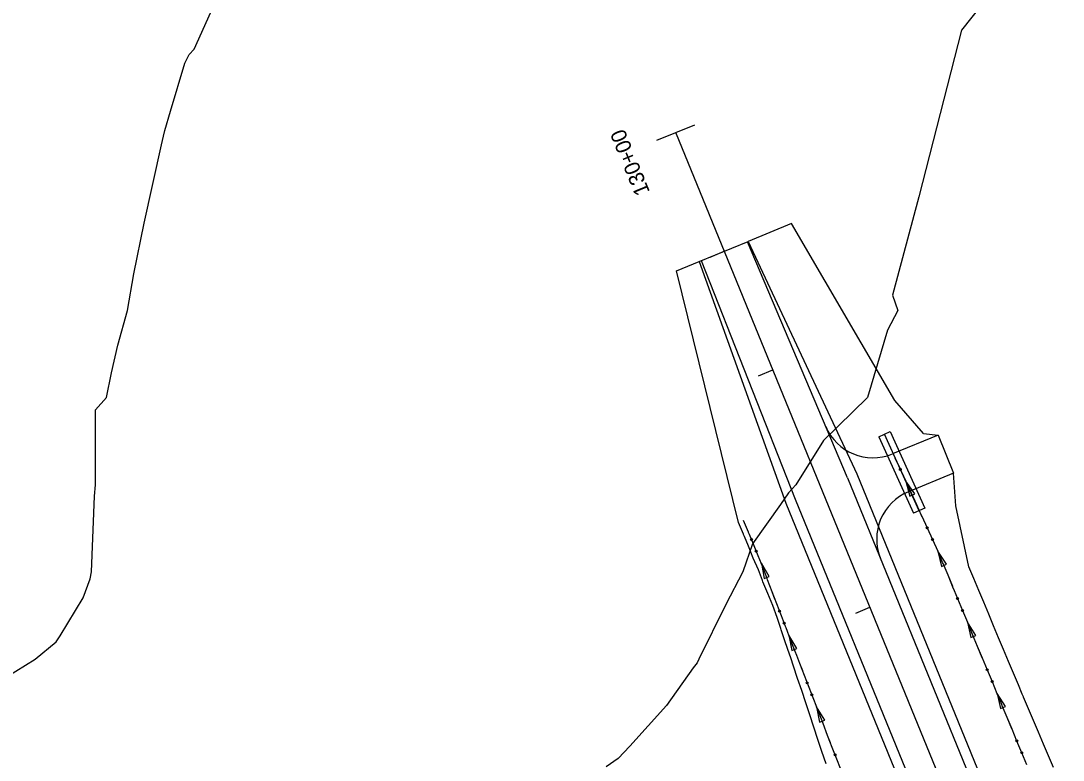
# Model space of a CAD drawing. Extents: x 916431 to 921570, y 1763982 to 1768032.
# Drawn here: x 918187 to 918593.5, y 1765886.5 to 1766174.8 of the extents above; entities that cross this region are included whole.
import ezdxf

# ---------------------------------------------------------------- set-up
doc = ezdxf.new("R2010")
doc.units = 0
for name, color, linetype in [('R_Drainage', 7, 'Continuous'), ('R_Horz Alg', 7, 'Continuous'), ('R_Horz Alg Stationing', 7, 'Continuous'), ('R_Proposed Const Limits', 7, 'Continuous'), ('R_Proposed Road', 7, 'Continuous'), ('R_SFHA', 7, 'Continuous'), ('R_Shld', 7, 'Continuous'), ('R_Special Ditch', 7, 'Continuous')]:
    doc.layers.add(name, color=color, linetype=linetype)

msp = doc.modelspace()

# ---------------------------------------------------------------- linework, layer by layer
at = {"layer": 'R_Drainage'}
for p, q in [((918523.8, 1766013.64), (918526, 1766014.64)), ((918526, 1766014.64), (918539.56, 1765984.79)), ((918521.6, 1766012.64), (918523.8, 1766013.64)), ((918521.6, 1766012.64), (918535.16, 1765982.79)), ((918537.36, 1765983.79), (918523.8, 1766013.64)), ((918539.56, 1765984.79), (918535.16, 1765982.79))]:
    msp.add_line(p, q, dxfattribs=at)
at = {"layer": 'R_Horz Alg'}
msp.add_line((918565.23, 1765830.96), (918442.38, 1766131.25), dxfattribs=at)
at = {"layer": 'R_Horz Alg Stationing'}
for points in [[(918434.97, 1766128.22), (918449.78, 1766134.28)], [(918474.69, 1766036.42), (918480.24, 1766038.7)], [(918512.55, 1765943.87), (918518.11, 1765946.14)]]:
    msp.add_lwpolyline(points, dxfattribs=at)
at = {"layer": 'R_Proposed Const Limits'}
for p, q in [((918539.04, 1766013.83), (918544.69, 1766013.2)), ((918551.55, 1765985.72), (918550.75, 1765998.39)), ((918556.72, 1765961.94), (918551.55, 1765985.72))]:
    msp.add_line(p, q, dxfattribs=at)
for points in [[(918539.04, 1766013.83), (918527.87, 1766026.76), (918487.58, 1766095.72), (918470.65, 1766088.8)], [(918466.82, 1765979.18), (918442.63, 1766077.33), (918451.49, 1766080.96)], [(918500.99, 1765885.12), (918499.38, 1765889.86), (918497.81, 1765894.62), (918496.27, 1765899.4), (918494.66, 1765904.14), (918493.13, 1765908.91), (918491.51, 1765913.65), (918489.9, 1765918.4), (918488.34, 1765923.16), (918487.24, 1765926.36), (918486.71, 1765927.9), (918485.09, 1765932.64), (918483.5, 1765937.39), (918483.35, 1765937.82), (918481.87, 1765942.12), (918480.22, 1765946.85), (918478.32, 1765951.47), (918476.4, 1765956.09), (918476.19, 1765956.6), (918474.59, 1765960.75), (918472.59, 1765965.34), (918470.69, 1765969.96), (918469.19, 1765973.67), (918468.83, 1765974.52), (918468.8, 1765974.59), (918466.82, 1765979.18)], [(918589.75, 1765883.61), (918587.74, 1765888.2), (918585.75, 1765892.78), (918583.82, 1765897.4), (918581.89, 1765902.01), (918579.91, 1765906.6), (918578.02, 1765911.12), (918577.98, 1765911.21), (918577.54, 1765912.28), (918576.06, 1765915.83), (918574.08, 1765920.42), (918572.16, 1765925.04), (918570.24, 1765929.66), (918568.28, 1765934.26), (918566.36, 1765938.87), (918564.44, 1765943.49), (918562.49, 1765948.09), (918560.57, 1765952.71), (918559.28, 1765955.83), (918558.66, 1765957.33), (918556.72, 1765961.94)]]:
    msp.add_lwpolyline(points, dxfattribs=at)
at = {"layer": 'R_Proposed Road'}
for p, q in [((918451.49, 1766080.96), (918470.65, 1766088.8)), ((918509.35, 1765996.59), (918470.32, 1766088.66)), ((918452.29, 1766081.28), (918488.99, 1765988.25)), ((918544.69, 1766013.2), (918526.85, 1766005.9)), ((918544.69, 1766013.2), (918550.75, 1765998.39)), ((918550.75, 1765998.39), (918533.17, 1765991.2)), ((918509.35, 1765996.59), (918575.41, 1765835.12)), ((918488.99, 1765988.25), (918555.05, 1765826.79))]:
    msp.add_line(p, q, dxfattribs=at)
for centre, start, end in [((918519.28, 1766024.42), 202.9725, 292.2503), ((918540.74, 1765972.69), 112.2503, 202.2503)]:
    msp.add_arc(centre, 20, start, end, dxfattribs=at)
at = {"layer": 'R_SFHA'}
for points in [[(918593.47, 1766221.24), (918553.81, 1766171.17), (918537.22, 1766106.16), (918526.91, 1766067.79), (918529.03, 1766061.85), (918524.91, 1766054.15), (918517.2, 1766027.89), (918499.95, 1766011.15), (918489.2, 1765993.9), (918486.31, 1765990.76), (918483.2, 1765986.16), (918472.27, 1765970.87), (918468.52, 1765959.93), (918461.9, 1765947.2), (918451.4, 1765925.92), (918450.72, 1765924.41), (918449.22, 1765922.53), (918438.71, 1765907.78), (918424.42, 1765891.92), (918419.93, 1765887.21), (918415.21, 1765883.98)], [(918177.34, 1765916.53), (918192.52, 1765925.91), (918200.74, 1765932.64), (918202.25, 1765935), (918211.29, 1765949.77), (918213.98, 1765957.24), (918214.52, 1765959.92), (918215.71, 1765989.5), (918216.12, 1765993.88), (918216.08, 1766023.11), (918220.32, 1766027.88), (918222.27, 1766037.55), (918224.8, 1766048.38), (918228.58, 1766061.88), (918231.05, 1766076.12), (918235.12, 1766095.84), (918241.87, 1766126.44), (918242.57, 1766129.85), (918243.16, 1766131.98), (918245.29, 1766139.51), (918250.87, 1766158.23), (918252.59, 1766161.63), (918254.6, 1766163.8), (918262.29, 1766180.79)]]:
    msp.add_lwpolyline(points, dxfattribs=at)
at = {"layer": 'R_Shld'}
for p, q in [((918470.65, 1766088.8), (918513.06, 1765998.1)), ((918455.75, 1766082.7), (918461.31, 1766084.97)), ((918451.49, 1766080.96), (918485.29, 1765986.74)), ((918513.06, 1765998.1), (918579.11, 1765836.64)), ((918485.29, 1765986.74), (918551.35, 1765825.28))]:
    msp.add_line(p, q, dxfattribs=at)
at = {"layer": 'R_Special Ditch'}
for p, q in [((918532.09, 1765995.33), (918533.64, 1765989.43)), ((918535.56, 1765990.31), (918532.09, 1765995.33)), ((918533.64, 1765989.43), (918535.56, 1765990.31)), ((918544.63, 1765968.03), (918545.96, 1765962.08)), ((918547.91, 1765962.9), (918544.63, 1765968.03)), ((918475.84, 1765963.39), (918476.83, 1765957.38)), ((918478.82, 1765958.08), (918475.84, 1765963.39)), ((918545.96, 1765962.08), (918547.91, 1765962.9)), ((918476.83, 1765957.38), (918478.82, 1765958.08)), ((918556.17, 1765940.3), (918557.5, 1765934.35)), ((918559.46, 1765935.16), (918556.17, 1765940.3)), ((918486.48, 1765935.31), (918487.66, 1765929.33)), ((918489.63, 1765930.09), (918486.48, 1765935.31)), ((918557.5, 1765934.35), (918559.46, 1765935.16)), ((918487.66, 1765929.33), (918489.63, 1765930.09)), ((918567.71, 1765912.56), (918569.04, 1765906.62)), ((918571, 1765907.43), (918567.71, 1765912.56)), ((918497.32, 1765907.29), (918498.49, 1765901.31)), ((918500.47, 1765902.08), (918497.32, 1765907.29)), ((918569.04, 1765906.62), (918571, 1765907.43)), ((918498.49, 1765901.31), (918500.47, 1765902.08))]:
    msp.add_line(p, q, dxfattribs=at)
for points in [[(918579.29, 1765884.74), (918577.37, 1765889.36), (918575.45, 1765893.97), (918573.53, 1765898.59), (918571.61, 1765903.2), (918569.73, 1765907.73), (918569.69, 1765907.82), (918569.24, 1765908.89), (918567.77, 1765912.44), (918565.85, 1765917.05), (918563.92, 1765921.67), (918562, 1765926.29), (918560.08, 1765930.9), (918558.16, 1765935.52), (918556.24, 1765940.14), (918554.32, 1765944.75), (918552.4, 1765949.37), (918551.1, 1765952.49), (918550.48, 1765953.98), (918548.56, 1765958.6), (918546.63, 1765963.22), (918546.46, 1765963.63), (918544.71, 1765967.83), (918542.63, 1765972.38), (918540.54, 1765976.93), (918538.45, 1765981.48), (918538.22, 1765981.98), (918536.36, 1765986.03), (918534.28, 1765990.57), (918532.19, 1765995.12), (918530.52, 1765998.76), (918530.13, 1765999.6), (918530.1, 1765999.67), (918528.01, 1766004.22)], [(918538.35, 1765981.69), (918538.22, 1765981.98), (918536.36, 1765986.03), (918534.28, 1765990.57), (918532.19, 1765995.12), (918532.09, 1765995.33)], [(918506.61, 1765883.26), (918505.22, 1765886.85), (918503.42, 1765891.51), (918501.61, 1765896.18), (918499.81, 1765900.84), (918498.01, 1765905.51), (918496.2, 1765910.17), (918494.4, 1765914.83), (918492.59, 1765919.5), (918490.79, 1765924.16), (918489.57, 1765927.31), (918488.99, 1765928.83), (918487.18, 1765933.49), (918485.38, 1765938.16), (918485.22, 1765938.58), (918483.58, 1765942.82), (918481.77, 1765947.48), (918479.97, 1765952.15), (918478.16, 1765956.81), (918477.97, 1765957.33), (918476.49, 1765961.53), (918474.58, 1765966.15), (918472.68, 1765970.77), (918471.15, 1765974.47), (918470.8, 1765975.32), (918470.77, 1765975.4), (918468.86, 1765980.02)], [(918470, 1765977.26), (918468.86, 1765980.02)], [(918538.37, 1765981.66), (918538.35, 1765981.69)], [(918470.02, 1765977.22), (918470, 1765977.26)], [(918550.4, 1765954.18), (918548.56, 1765958.6), (918546.63, 1765963.22), (918546.46, 1765963.63), (918544.71, 1765967.83), (918544.63, 1765968.03)], [(918481.06, 1765949.33), (918479.97, 1765952.15), (918478.16, 1765956.81), (918477.97, 1765957.33), (918476.49, 1765961.53), (918475.74, 1765963.35)], [(918550.41, 1765954.14), (918550.4, 1765954.18)], [(918481.07, 1765949.3), (918481.06, 1765949.33)], [(918561.94, 1765926.45), (918560.08, 1765930.9), (918558.16, 1765935.52), (918556.24, 1765940.14), (918556.17, 1765940.3)], [(918491.89, 1765921.32), (918490.79, 1765924.16), (918489.57, 1765927.31), (918488.99, 1765928.83), (918487.18, 1765933.49), (918486.48, 1765935.31)], [(918561.95, 1765926.41), (918561.94, 1765926.45)], [(918491.91, 1765921.28), (918491.89, 1765921.32)], [(918573.48, 1765898.71), (918571.61, 1765903.2), (918569.73, 1765907.73), (918569.69, 1765907.82), (918569.24, 1765908.89), (918567.77, 1765912.44), (918567.71, 1765912.56)], [(918502.73, 1765893.3), (918501.61, 1765896.18), (918499.81, 1765900.84), (918498.01, 1765905.51), (918497.32, 1765907.29)], [(918573.49, 1765898.68), (918573.48, 1765898.71)], [(918502.74, 1765893.26), (918502.73, 1765893.3)]]:
    msp.add_lwpolyline(points, dxfattribs=at)
for centre in [(918529.97, 1765999.86), (918540.41, 1765977.11), (918471.88, 1765972.6), (918542.5, 1765972.56), (918473.79, 1765967.97), (918552.29, 1765949.53), (918554.22, 1765944.9), (918482.84, 1765944.63), (918484.64, 1765939.96), (918563.83, 1765921.8), (918493.67, 1765916.62), (918565.76, 1765917.17), (918495.48, 1765911.95), (918575.37, 1765894.06), (918504.5, 1765888.6), (918577.3, 1765889.44)]:
    msp.add_circle(centre, 0.375, dxfattribs=at)

# ---------------------------------------------------------------- texts
at = {"layer": 'R_Horz Alg Stationing'}
msp.add_text('130+00', height=6, rotation=112.2503, dxfattribs=at).set_placement((918432.4, 1766108.1))

doc.saveas('drawing.dxf')
